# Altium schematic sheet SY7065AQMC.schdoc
size 127 x 101 mm
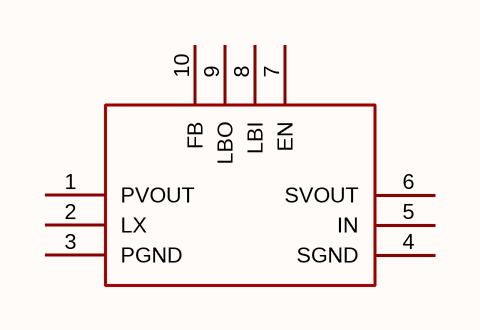
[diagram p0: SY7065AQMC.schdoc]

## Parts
U?  sy7065aqmc  [QFN-10_L2.0-W2.0_SY7066AQMC]  (value not drawn)

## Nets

Not connected (* = marked no-connect by the designer): U? 1(PVOUT) 2(LX) 3(PGND) 4(SGND) 5(IN) 6(SVOUT) 7(EN) 8(LBI) 9(LBO) 10(FB)

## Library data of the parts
U? = sy7065aqmc: 功能类型:升压型;工作电压:1.8V~5.25V;输出电压:2.5V~5.5V;输出电流:5A;输出类型:可调;; Manufacturer: Silergy(矽力杰); AddInBom: yes; ModelId: 6bdd6ce538564a8d848b5bb8ea49d3d0; ModelName: QFN-10_L2.0-W2.0-H0.7_SY7066AQMC; ModelTransform: 79.527,79.1337,0,0,0,0,-2.241,-2.761,0; Function: 升压型; Output Current: 5A; Frequency - Switching: 500kHz; Synchronous Rectifier: 是; Number of Outputs: 1; Topology: 升压式; Quiescent Current: 27uA; Switch tube (built-in/external): 内置; Output Type: 可调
